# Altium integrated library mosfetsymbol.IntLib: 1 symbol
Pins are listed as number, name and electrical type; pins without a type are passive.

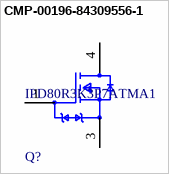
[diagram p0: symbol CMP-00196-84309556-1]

## CMP-00196-84309556-1
designator Q?, comment IPD80R3K3P7ATMA1
IPD80R3K3P7ATMA1 Transistor MOSFET N-CH 800V 1.9A 3-Pin TO-252 T/R - Tape and Reel; NexarPartId: 84309556; Gate to Source Voltage (Vgs): 20V; Max Junction Temperature (Tj): 150°C; Power Dissipation: 18W; Number of Channels: 1; Turn-On Delay Time: 12ns; Drain to Source Resistance: 2.8Ω; Turn-Off Delay Time: 40ns; On-State Resistance: 3.3Ω
footprint FP-PG-TO252-3-MFG
pins: 1 Gate, 3 Source, 4 Drain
